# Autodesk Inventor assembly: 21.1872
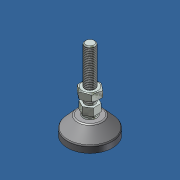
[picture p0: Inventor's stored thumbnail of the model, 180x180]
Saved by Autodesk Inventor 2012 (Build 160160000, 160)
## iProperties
Created: 2007-03
Part Number: 21.1872
Document SubType Name: Assembly
Designer: Andy Moles
Description: LEVELING FOOT M10 45mm BASE
Author: Andy Moles
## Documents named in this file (5)
- C:\Andys Backup Data\ANDY'S INVENTOR\INVENTOR LIBRARIES\PARTS LIBRARY\FEET WHEELS FLOOR FASTENING SUPPORTS\21.1872 LEVELING FOOT M10 45mm BASE.iam
- C:\Andys Backup Data\ANDY'S INVENTOR\INVENTOR LIBRARIES\PARTS LIBRARY\FASTENING ELEMENTS\NUTS\21.1527 M10 HEX NUT.ipt
- C:\Andys Backup Data\ANDY'S INVENTOR\INVENTOR LIBRARIES\PARTS LIBRARY\FEET WHEELS FLOOR FASTENING SUPPORTS\SUBCOMPONENTS\LEVELING FEET SUBCOMPONENTS\PAD 45mm PLASTIC.ipt
- C:\Andys Backup Data\ANDY'S INVENTOR\INVENTOR LIBRARIES\PARTS LIBRARY\FEET WHEELS FLOOR FASTENING SUPPORTS\SUBCOMPONENTS\LEVELING FEET SUBCOMPONENTS\ANTI-SKID PAD 45mm.ipt
- C:\Andys Backup Data\ANDY'S INVENTOR\INVENTOR LIBRARIES\PARTS LIBRARY\FEET WHEELS FLOOR FASTENING SUPPORTS\SUBCOMPONENTS\LEVELING FEET SUBCOMPONENTS\THREADED STUD 10mm LONGER.ipt
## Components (4 placed, 4 different names)
1. ANTI-SKID PAD 45mm:1 — Insert:1
2. PAD 45mm PLASTIC:1 — Insert:1, Tangent:1, Mate:1
3. THREADED STUD 10mm LONGER:1 — Tangent:1, Mate:1, Mate:2
4. 21.1527 M10 HEX NUT:1 — Mate:2
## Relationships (4: Mate 2, Insert 1, Tangent 1)
- Insert:1: ANTI-SKID PAD 45mm:1 ↔ PAD 45mm PLASTIC:1
- Tangent:1: PAD 45mm PLASTIC:1 ↔ THREADED STUD 10mm LONGER:1
- Mate:1: PAD 45mm PLASTIC:1 ↔ THREADED STUD 10mm LONGER:1
- Mate:2: THREADED STUD 10mm LONGER:1 ↔ 21.1527 M10 HEX NUT:1
